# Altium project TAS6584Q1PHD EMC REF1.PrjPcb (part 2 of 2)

## Sheet PowerSupplies_Powerstage.SchDoc: Power Supplies
size Letter; Date: Not shown in title block; ApprovedBy: Not shown in title block; CheckedBy: Not shown in title block; Author: Not shown in title block; CompanyName: Not shown in title block; DrawnBy: LDN; Engineer: Not shown in title block; Organization: Not shown in title block; Address1: Not shown in title block; Address2: Not shown in title block; Address3: Not shown in title block; Address4: Not shown in title block; DocumentNumber: 3; Revision: Use project parameter SCH_Rev; SheetNumber: 3; SheetTotal: 4; PageSetup: Record=PageOptions¦CenterHorizontal=True¦CenterVertical=True¦PrintScale=1.00¦XCorrection=1.00¦YCorrection=1.00¦PrintKind=0¦BorderSize=5000000¦LeftOffset=0¦BottomOffset=0¦Orientation=2¦PaperLength=1000¦PaperWidth=1000¦Scale=100¦PaperSource=15¦PrintQuality=600¦MediaType=1¦DitherType=10¦PaperKind=Letter¦PrintScaleMode=1
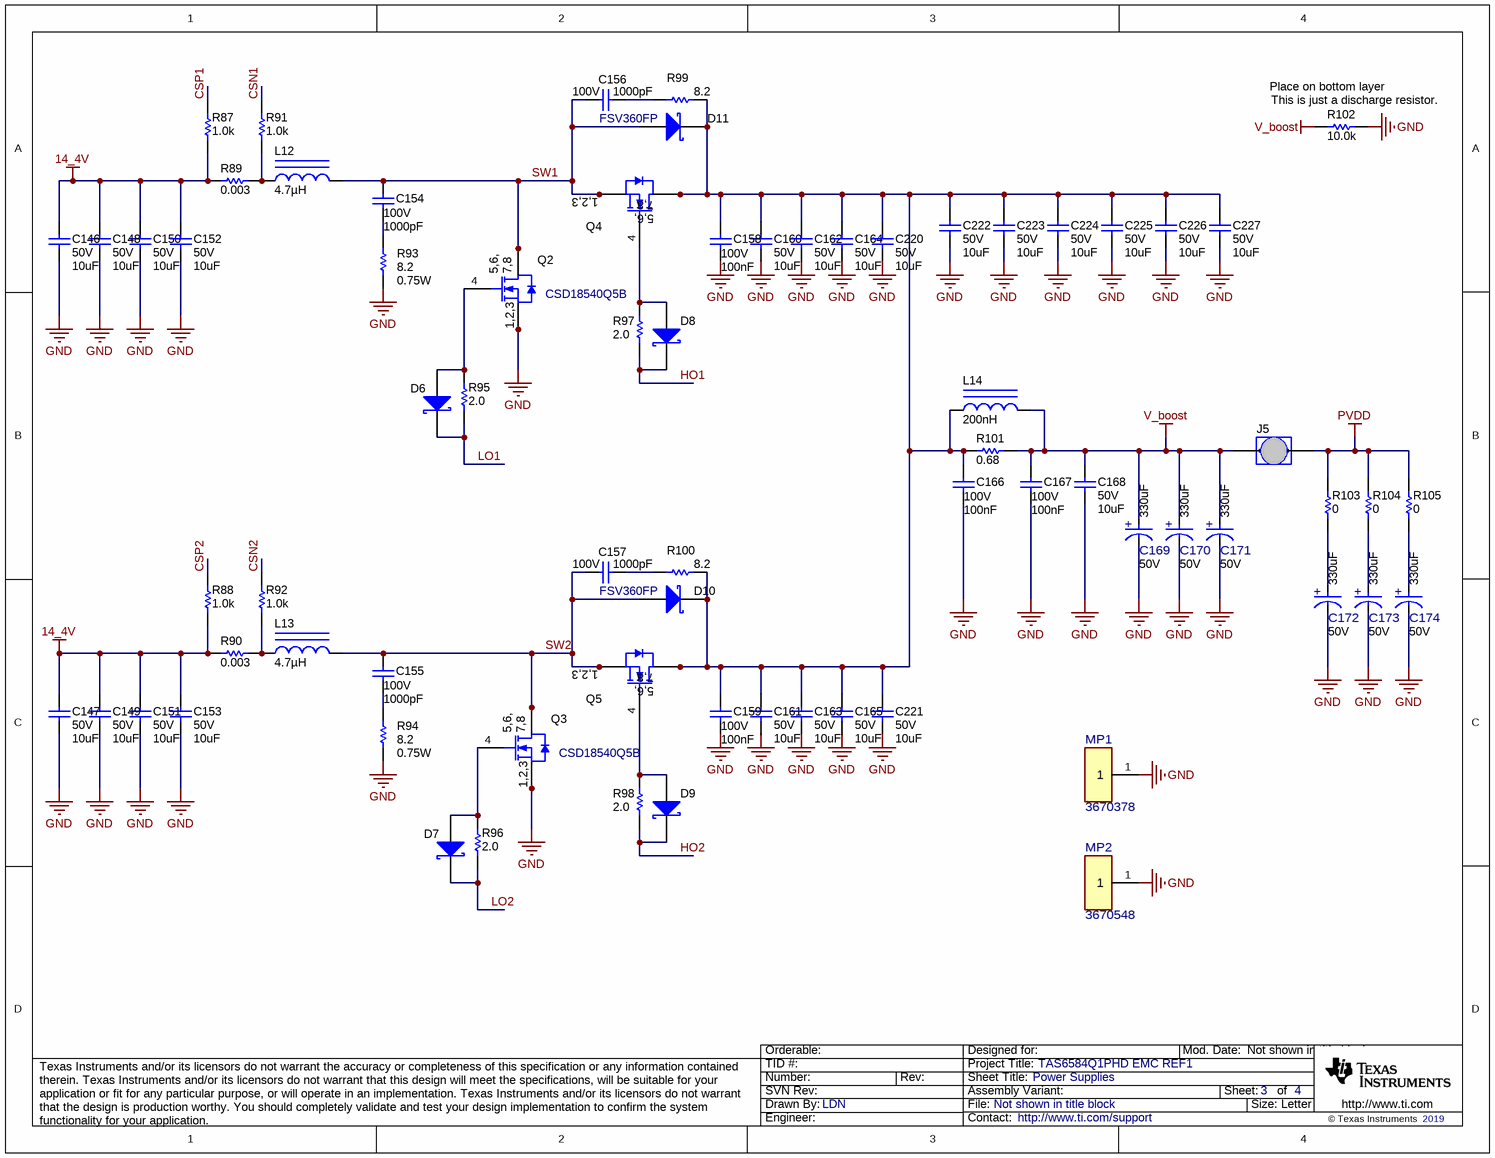
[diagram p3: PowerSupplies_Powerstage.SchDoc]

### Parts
C146  VDC_V: 50V  ValueDisplayed: 10uF  [1210_270]  (hidden comment: GRM32ER71H106KA12L)
C147  VDC_V: 50V  ValueDisplayed: 10uF  [1210_270]  (hidden comment: GRM32ER71H106KA12L)
C148  VDC_V: 50V  ValueDisplayed: 10uF  [1210_270]  (hidden comment: GRM32ER71H106KA12L)
C149  VDC_V: 50V  ValueDisplayed: 10uF  [1210_270]  (hidden comment: GRM32ER71H106KA12L)
C150  VDC_V: 50V  ValueDisplayed: 10uF  [1210_270]  (hidden comment: GRM32ER71H106KA12L)
C151  VDC_V: 50V  ValueDisplayed: 10uF  [1210_270]  (hidden comment: GRM32ER71H106KA12L)
C152  VDC_V: 50V  ValueDisplayed: 10uF  [1210_270]  (hidden comment: GRM32ER71H106KA12L)
C153  VDC_V: 50V  ValueDisplayed: 10uF  [1210_270]  (hidden comment: GRM32ER71H106KA12L)
C154  VDC_V: 100V  ValueDisplayed: 1000pF  [0603L]  (hidden comment: GCM1885C2A102JA16D)
C155  VDC_V: 100V  ValueDisplayed: 1000pF  [0603L]  (hidden comment: GCM1885C2A102JA16D)
C156  VDC_V: 100V  ValueDisplayed: 1000pF  [0603L]  (hidden comment: GCM1885C2A102JA16D)
C157  VDC_V: 100V  ValueDisplayed: 1000pF  [0603L]  (hidden comment: GCM1885C2A102JA16D)
C158  Cap_F: 100nF  VDC_V: 100V  [0603L]  (hidden comment: GRM188R72A104KA35J)
C159  Cap_F: 100nF  VDC_V: 100V  [0603L]  (hidden comment: GRM188R72A104KA35J)
C160  VDC_V: 50V  ValueDisplayed: 10uF  [1210_270]  (hidden comment: GRM32ER71H106KA12L)
C161  VDC_V: 50V  ValueDisplayed: 10uF  [1210_270]  (hidden comment: GRM32ER71H106KA12L)
C162  VDC_V: 50V  ValueDisplayed: 10uF  [1210_270]  (hidden comment: GRM32ER71H106KA12L)
C163  VDC_V: 50V  ValueDisplayed: 10uF  [1210_270]  (hidden comment: GRM32ER71H106KA12L)
C164  VDC_V: 50V  ValueDisplayed: 10uF  [1210_270]  (hidden comment: GRM32ER71H106KA12L)
C165  VDC_V: 50V  ValueDisplayed: 10uF  [1210_270]  (hidden comment: GRM32ER71H106KA12L)
C166  Cap_F: 100nF  VDC_V: 100V  [0603L]  (hidden comment: GRM188R72A104KA35J)
C167  Cap_F: 100nF  VDC_V: 100V  [0603L]  (hidden comment: GRM188R72A104KA35J)
C168  VDC_V: 50V  ValueDisplayed: 10uF  [1210_270]  (hidden comment: GRM32ER71H106KA12L)
C169  ValueDisplayed: 330uF  VDC_V: 50V  [FP-EMZR500ARA331MJA0G_RADIAL-MFG]  (hidden comment: EMZR500ARA331MJA0G)
C170  ValueDisplayed: 330uF  VDC_V: 50V  [FP-EMZR500ARA331MJA0G_RADIAL-MFG]  (hidden comment: EMZR500ARA331MJA0G)
C171  ValueDisplayed: 330uF  VDC_V: 50V  [FP-EMZR500ARA331MJA0G_RADIAL-MFG]  (hidden comment: EMZR500ARA331MJA0G)
C172  ValueDisplayed: 330uF  VDC_V: 50V  [FP-EMZR500ARA331MJA0G_RADIAL-MFG]  (hidden comment: EMZR500ARA331MJA0G)
C173  ValueDisplayed: 330uF  VDC_V: 50V  [FP-EMZR500ARA331MJA0G_RADIAL-MFG]  (hidden comment: EMZR500ARA331MJA0G)
C174  ValueDisplayed: 330uF  VDC_V: 50V  [FP-EMZR500ARA331MJA0G_RADIAL-MFG]  (hidden comment: EMZR500ARA331MJA0G)
C220  VDC_V: 50V  ValueDisplayed: 10uF  [1210_270]  (hidden comment: GRM32ER71H106KA12L)
C221  VDC_V: 50V  ValueDisplayed: 10uF  [1210_270]  (hidden comment: GRM32ER71H106KA12L)
C222  VDC_V: 50V  ValueDisplayed: 10uF  [1210_270]  (hidden comment: GRM32ER71H106KA12L)
C223  VDC_V: 50V  ValueDisplayed: 10uF  [1210_270]  (hidden comment: GRM32ER71H106KA12L)
C224  VDC_V: 50V  ValueDisplayed: 10uF  [1210_270]  (hidden comment: GRM32ER71H106KA12L)
C225  VDC_V: 50V  ValueDisplayed: 10uF  [1210_270]  (hidden comment: GRM32ER71H106KA12L)
C226  VDC_V: 50V  ValueDisplayed: 10uF  [1210_270]  (hidden comment: GRM32ER71H106KA12L)
C227  VDC_V: 50V  ValueDisplayed: 10uF  [1210_270]  (hidden comment: GRM32ER71H106KA12L)
D6  BAT54HT1G  [SOD-323]  (value not drawn)
D7  BAT54HT1G  [SOD-323]  (value not drawn)
D8  BAT54HT1G  [SOD-323]  (value not drawn)
D9  BAT54HT1G  [SOD-323]  (value not drawn)
D10  FSV360FP  [SOD-123HE]
D11  FSV360FP  [SOD-123HE]
J5  (no value)  [HARWIN_S1911-46R]
L12  ValueDisplayed: 4.7µH  [SRP1770TA]  (hidden comment: SRP1770TA-4R7M)
L13  ValueDisplayed: 4.7µH  [SRP1770TA]  (hidden comment: SRP1770TA-4R7M)
L14  ValueDisplayed: 200nH  [SRP7030F_3]  (hidden comment: SRP7030-R20FM)
MP1  3670378  [FP-3670378_RF_SHIELD-MFG]
MP2  3670548  [FP-3670548_RF_SHIELD-MFG]
Q2  CSD18540Q5B  [DNK0008A]
Q3  CSD18540Q5B  [DNK0008A]
Q4  CSD18540Q5B  [DNK0008A]  (value not drawn)
Q5  CSD18540Q5B  [DNK0008A]  (value not drawn)
R87  ValueDisplayed: 1.0k  [0402L]  (hidden comment: CRCW04021K00JNED)
R88  ValueDisplayed: 1.0k  [0402L]  (hidden comment: CRCW04021K00JNED)
R89  ValueDisplayed: 0.003  [PA2512]  (hidden comment: PA2512FKF070R003E)
R90  ValueDisplayed: 0.003  [PA2512]  (hidden comment: PA2512FKF070R003E)
R91  ValueDisplayed: 1.0k  [0402L]  (hidden comment: CRCW04021K00JNED)
R92  ValueDisplayed: 1.0k  [0402L]  (hidden comment: CRCW04021K00JNED)
R93  Value2: 0.75W  ValueDisplayed: 8.2  [2010]  (hidden comment: CRCW20108R20JNEF)
R94  Value2: 0.75W  ValueDisplayed: 8.2  [2010]  (hidden comment: CRCW20108R20JNEF)
R95  ValueDisplayed: 2.0  [0603]  (hidden comment: CRCW06032R00JNEA)
R96  ValueDisplayed: 2.0  [0603]  (hidden comment: CRCW06032R00JNEA)
R97  ValueDisplayed: 2.0  [0603]  (hidden comment: CRCW06032R00JNEA)
R98  ValueDisplayed: 2.0  [0603]  (hidden comment: CRCW06032R00JNEA)
R99  ValueDisplayed: 8.2  [2010]  (hidden comment: CRCW20108R20JNEF)
R100  ValueDisplayed: 8.2  [2010]  (hidden comment: CRCW20108R20JNEF)
R101  ValueDisplayed: 0.68  [2512]  (hidden comment: ERJ-1TRQJR68U)
R102  ValueDisplayed: 10.0k  [2512]  (hidden comment: CRCW251210K0FKEG)
R103  ValueDisplayed: 0  [1210]  (hidden comment: MCR25JZHJ000)
R104  ValueDisplayed: 0  [1210]  (hidden comment: MCR25JZHJ000)
R105  ValueDisplayed: 0  [1210]  (hidden comment: MCR25JZHJ000)

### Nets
14_4V: C146.1 C147.1 C148.1 C149.1 C150.1 C151.1 C152.1 C153.1 R87.1 R88.1 R89.1 R90.1
GND: C146.2 C147.2 C148.2 C149.2 C150.2 C151.2 C152.2 C153.2 C158.2 C159.2 C160.2 C161.2 C162.2 C163.2 C164.2 C165.2 C166.2 C167.2 C168.2 C169.1(CATHODE) C170.1(CATHODE) C171.1(CATHODE) C172.1(CATHODE) C173.1(CATHODE) C174.1(CATHODE) C220.2 C221.2 C222.2 C223.2 C224.2 C225.2 C226.2 C227.2 MP1.1 MP2.1 Q2.1(S) Q2.2(S) Q2.3(S) Q3.1(S) Q3.2(S) Q3.3(S) R93.1 R94.1 R102.2
PVDD: J5.2 R103.2 R104.2 R105.2
V_boost: C167.1 C168.1 C169.2(ANODE) C170.2(ANODE) C171.2(ANODE) J5.1 L14.2 R101.2 R102.1
CSN1: R91.2
CSN2: R92.2
CSP1: R87.2
CSP2: R88.2
HO1: D8.1(K) R97.1
HO2: D9.1(K) R98.1
LO1: D6.1(K) R95.1
LO2: D7.1(K) R96.1
SW1: C154.1 C156.1 D11.2(A) L12.2 Q2.5(D) Q2.6(D) Q2.7(D) Q2.8(D) Q2.9(D) Q4.1(S) Q4.2(S) Q4.3(S)
SW2: C155.1 C157.1 D10.2(A) L13.2 Q3.5(D) Q3.6(D) Q3.7(D) Q3.8(D) Q3.9(D) Q5.1(S) Q5.2(S) Q5.3(S)
NetC154_2: C154.2 R93.2
NetC155_2: C155.2 R94.2
NetC156_2: C156.2 R99.1
NetC157_2: C157.2 R100.1
NetC158_1: C158.1 C159.1 C160.1 C161.1 C162.1 C163.1 C164.1 C165.1 C166.1 C220.1 C221.1 C222.1 C223.1 C224.1 C225.1 C226.1 C227.1 D10.1(K) D11.1(K) L14.1 Q4.5(D) Q4.6(D) Q4.7(D) Q4.8(D) Q4.9(D) Q5.5(D) Q5.6(D) Q5.7(D) Q5.8(D) Q5.9(D) R99.2 R100.2 R101.1
NetC172_2: C172.2(ANODE) R103.1
NetC173_2: C173.2(ANODE) R104.1
NetC174_2: C174.2(ANODE) R105.1
NetD6_2: D6.2(A) Q2.4(G) R95.2
NetD7_2: D7.2(A) Q3.4(G) R96.2
NetD8_2: D8.2(A) Q4.4(G) R97.2
NetD9_2: D9.2(A) Q5.4(G) R98.2
NetL12_1: L12.1 R89.2 R91.1
NetL13_1: L13.1 R90.2 R92.1

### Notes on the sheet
- (near R102) Place on bottom layer
- (near R102) This is just a discharge resistor.

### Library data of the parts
C146-C153 C160-C165 C168 C220-C227 = CMP-0009226-3: CAP, CERM, 10 uF, 50 V, +/- 10%, X7R, 1210; Manufacturer: MuRata; TaMin_C: -55°C; Polarized: N; SizeAreaWB_mm2: 14.7; Value1: Unknown; U/M: EA; Value: 10uF; TaMax_C: 125°C; SizeZ_mm: 2.7; SizeX_mm: 3.2; SizeY_mm: 2.5; Cap_Case: 1210; SizeArea_mm2: 8; Cap_F: 10µF; AEC Category: Q200
C154-C157 = CMP-0007131-1: CAP, CERM, 1000 pF, 100 V, +/- 5%, C0G/NP0, AEC-Q200 Grade 1, 0603; Manufacturer: MuRata; TaMin_C: -55°C; Polarized: N; SizeAreaWB_mm2: 4.68; Value1: Unknown; U/M: EA; Value: 1000pF; TaMax_C: 125°C; SizeZ_mm: 1; SizeX_mm: 1.6; SizeY_mm: 0.8; Cap_Case: 0603; SizeArea_mm2: 1.28; AEC Qualified: Y; Cap_F: 1nF; AEC Category: Q200
C158 C159 C166 C167 = CMP-0007470-1: CAP, CERM, 0.1 uF, 100 V, +/- 10%, X7R, 0603; Manufacturer: MuRata; TaMin_C: -55°C; Polarized: N; SizeAreaWB_mm2: 4.68; Value1: Unknown; U/M: EA; Value: 0.1uF; TaMax_C: 125°C; SizeZ_mm: 1; SizeX_mm: 1.6; SizeY_mm: 0.8; Cap_Case: 0603; SizeArea_mm2: 1.28; AEC Category: Q200
C169-C174 = CMP-0093066-1: 330 µF 50 V Aluminum Electrolytic Capacitors Radial, Can - SMD 120mOhm @ 100kHz 2000 Hrs @ 105°C; Manufacturer: United Chemi-Con; Dissipation Factor: 10%; Esr: 0.12; Value: 330µF; AEC Qualified: Yes; AEC Grade: Grade 2; IRMS_A: 900mA; Life: 2000Hours; Tolerance_%: 20%; SizeZ_mm: 10.3mm; Leakage Current: 165uA
D6-D9 = CMP-0028455-1: Diode, Schottky, 30 V, 0.2 A, SOD-323; Manufacturer: ON Semiconductor; Io_A: 200mA; Green_Lifecycle: Active; SizeAreaWB_mm2: 8.695; Vr_V: 30V; Green_REACh: Passed; Value1: 0.2A; U/M: EA; Value: 30V; SizeZ_mm: 1; SizeX_mm: 2.7; SizeY_mm: 1.35; Vf_V: 350mV; Value2: 0.35V; SizeArea_mm2: 3.645; AEC Category: Q101
D10 D11 = CMP-0028825-2: Diode, Schottky, 60 V, 3 A, AEC-Q101, SOD-123HE; Manufacturer: Fairchild Semiconductor; Vf_V: 650mV; SizeArea_mm2: 6.66; Vr_V: 60V; Green_Lifecycle: Not Set; Value: 60V; Value1: 3A; Green_REACh: Incomplete; SizeY_mm: 1.8; Value2: 0.65V; TJmax_C: 150°C; AEC Category: Q101; SizeAreaWB_mm2: 13.16; SizeZ_mm: 1; AEC Qualified: Y; SizeX_mm: 3.7
J5 = CMP-0075020-1: JUMPER TIN SMD; Manufacturer: Harwin; PartNumber: S1911-46R; CNHeader: False; Green_Lifecycle: Active; Green_REACh: Passed; CompType: Jumper SMT
L12 L13 = CMP-0081211-1: Inductor, Shielded, Powdered Iron, 4.7 µH, 25 A, 0.0055 ohm, AEC-Q200 Grade 0, SMD; Manufacturer: Bourns; Isat: 50A @ 30% inductance drop; Irms: 25A @ 40C rise; SizeAreaWB_mm2: 364.77; DCR_ohm: 5.5m; Value: 4.7uH; Imax_A: 25A; SizeZ_mm: 7; SizeX_mm: 17.3; SizeY_mm: 16.9; SizeArea_mm2: 292.37; AEC Qualified: Y; AEC Grade: 0; AEC Category: Q200
L14 = CMP-0056994-1: Inductor, Flat Wire, Powdered Iron, 200 nH, 23 A, 0.0024 ohm, SMD; Manufacturer: Bourns; Isat: 34A @ 20% inductance drop; Irms: 23A @ 40C rise; Green_Lifecycle: NRND; SizeAreaWB_mm2: 81.6; DCR_ohm: 2.4m; Green_REACh: Passed; Value: 200nH; Imax_A: 23A; SizeZ_mm: 3; SizeX_mm: 7.6; SizeY_mm: 6.5; SizeArea_mm2: 49.4; AEC Category: Q200
MP1 = CMP-0093198-1: Manufacturer: Wurth Electronics; SizeZ_mm: 3.2mm; AEC Qualified: No
MP2 = CMP-0093199-1: Manufacturer: Wurth Electronics; AEC Qualified: No; SizeZ_mm: 11.2mm
Q2-Q5 = CMP-0000823-2: MOSFET, N-CH, 60 V, 100 A, DNK0008A (VSON-CLIP-8); Alternate Manufacturer: None; Manufacturer: Texas Instruments; SizeZ_mm: 1; ChType: N; Value2: 41 nC; Value1: 0.003; VdsMax_V: 60V; SizeX_mm: 6; SizeY_mm: 5; Vgs_V: 20V; Value: 60V; Rdson45_ohm: 3.3m; SizeArea_mm2: 30; AEC Category: Q101; IdsMax_A: 100A; SizeAreaWB_mm2: 56; U/M: EA; QgTyp_nC: 41
R87 R88 R91 R92 = CMP-0026852-1: RES, 1.0 k, 5%, 0.063 W, 0402; Manufacturer: Vishay-Dale; Power_W: 63mW; TempCo: 200 ppm/C; Value_Code: 1k00; U/M: EA; Value: 1.0k; EIA_Code: E24; Res_ohm: 1k; SizeX_mm: 1; SizeY_mm: 0.5; SizeZ_mm: 0.6; Value2: 0.063W; VDC_V: 50V; AEC Category: Q200
R89 R90 = CMP-0015833-2: RES, 0.003, 1%, 1 W, AEC-Q200 Grade 0, 2512; Manufacturer: Yageo America; Power_W: 1W; TempCo: 100 ppm/C; Value_Code: 3L000; U/M: EA; Value: 0.003; EIA_Code: E96; Res_ohm: 3m; AEC Qualified: Y; AEC Grade: 0; AEC Category: Q200
R93 R94 = CMP-0016186-1: RES, 8.2, 5%, 0.75 W, AEC-Q200 Grade 0, 2010; Manufacturer: Vishay-Dale; Power_W: 750mW; TempCo: 200 ppm/C; Value_Code: 8R20; U/M: EA; Value: 8.2; EIA_Code: E24; SizeX_mm: 5; SizeY_mm: 2.5; SizeZ_mm: 1.66; SizeArea_mm2: 12.5; AEC Qualified: Y; VDC_V: 400V; AEC Grade: 0; AEC Category: Q200
R95-R98 = CMP-0025776-4: RES, 2.0, 5%, 0.1 W, AEC-Q200 Grade 0, 0603; Manufacturer: Vishay-Dale; Power_W: 100mW; TempCo: 200 ppm/C; Value_Code: 2R00; Value: 2.0; EIA_Code: E24; Res_ohm: 2; SizeX_mm: 1.6; SizeY_mm: 0.8; SizeZ_mm: 1; Value2: 0.1W; SizeArea_mm2: 1.28; AEC Qualified: Y; VDC_V: 75V; AEC Category: Q200; AEC Grade: 0
R99 R100 = CMP-0016186-1: RES, 8.2, 5%, 0.75 W, AEC-Q200 Grade 0, 2010; Manufacturer: Vishay-Dale; Power_W: 750mW; TempCo: 200 ppm/C; Value_Code: 8R20; U/M: EA; Value: 8.2; EIA_Code: E24; SizeX_mm: 5; SizeY_mm: 2.5; SizeZ_mm: 1.66; Value2: 0.75W; SizeArea_mm2: 12.5; AEC Qualified: Y; VDC_V: 400V; AEC Grade: 0; AEC Category: Q200
R101 = CMP-0016021-1: RES, 0.68, 5%, 1 W, 2512; Manufacturer: Panasonic; Power_W: 1W; TempCo: 200 ppm/C; Value_Code: R680; U/M: EA; Value: 0.68; SizeX_mm: 6.3; SizeY_mm: 3.2; SizeZ_mm: 0.71; SizeArea_mm2: 20.16; AEC Category: Q200
R102 = CMP-0015431-1: RES, 10.0 k, 1%, 1 W, AEC-Q200 Grade 0, 2512; Manufacturer: Vishay-Dale; Power_W: 1W; TempCo: 100 ppm/C; Value_Code: 10k0; U/M: EA; Value: 10.0k; EIA_Code: E96; Res_ohm: 10k; SizeX_mm: 6.3; SizeY_mm: 3.2; SizeZ_mm: 0.71; SizeArea_mm2: 20.16; AEC Qualified: Y; VDC_V: 500V; AEC Grade: 0; AEC Category: Q200
R103-R105 = CMP-0015361-2: RES, 0, 5%, 0.25 W, 1210; Manufacturer: Rohm; Power_W: 250mW; TempCo: 20 ppm/C; SizeAreaWB_mm2: 14.7; Value_Code: 0000; U/M: EA; Value: 0; EIA_Code: E24; SizeX_mm: 3.2; SizeY_mm: 2.5; SizeZ_mm: 1.35; Value2: 0.25W; SizeArea_mm2: 8; VDC_V: 200V; AEC Category: Q200

## Sheet SPDIF and Interface.SchDoc: SPDIF I/O
size 431 x 279 mm; Date: Not shown in title block; ApprovedBy: Not shown in title block; CheckedBy: Not shown in title block; Author: Not shown in title block; CompanyName: Not shown in title block; DrawnBy: LDN; Engineer: Not shown in title block; Organization: Not shown in title block; Address1: Not shown in title block; Address2: Not shown in title block; Address3: Not shown in title block; Address4: Not shown in title block; DocumentNumber: 1; SheetNumber: 1; SheetTotal: 4; PageSetup: Record=PageOptions¦CenterHorizontal=True¦CenterVertical=True¦PrintScale=0.98¦XCorrection=1.00¦YCorrection=1.00¦PrintKind=0¦BorderSize=5000000¦LeftOffset=0¦BottomOffset=0¦Orientation=2¦PaperLength=1000¦PaperWidth=1000¦Scale=100¦PaperSource=15¦PrintQuality=-3¦MediaType=1¦DitherType=10¦PrintScaleMode=1¦PaperKind=11 x 17¦PaperIndex=119
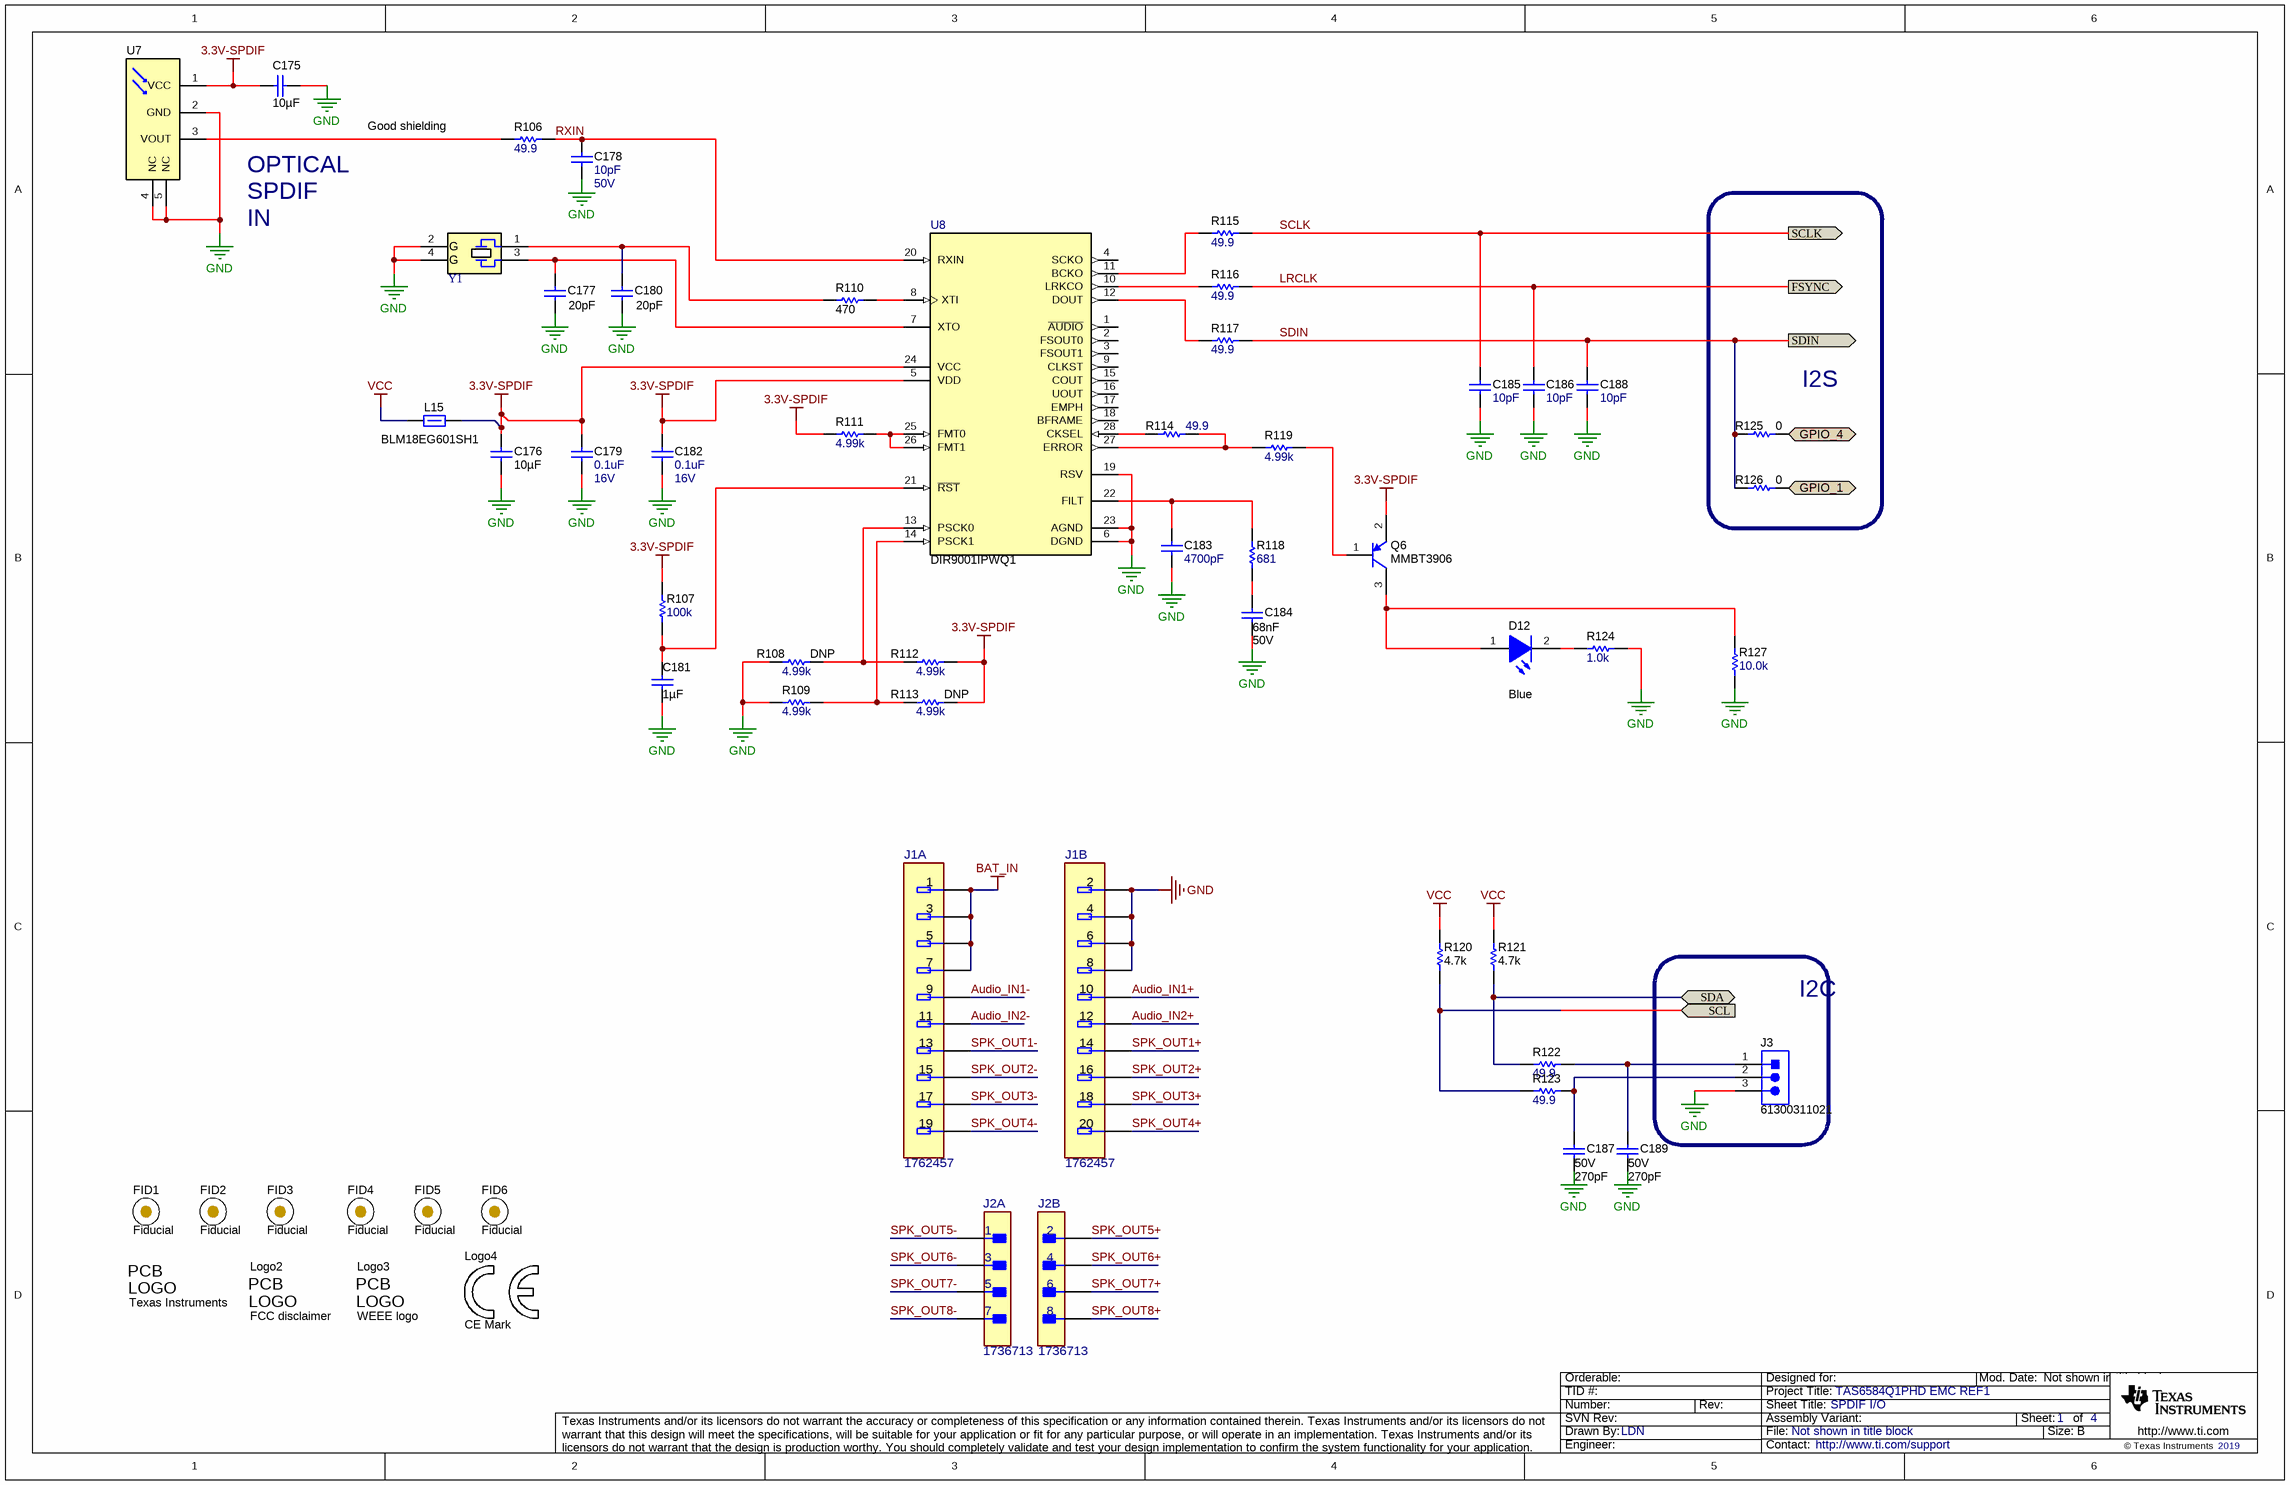
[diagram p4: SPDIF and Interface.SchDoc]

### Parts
C175  Cap_F: 10µF  [0603L]  (hidden comment: GRM188Z71A106MA73D)
C176  Cap_F: 10µF  [0603L]  (hidden comment: GRM188Z71A106MA73D)
C177  ValueDisplayed: 20pF  [0402L]  (hidden comment: GRM1555C1H200JA01D)
C178  ValueDisplayed: 10pF  VDC_V: 50V  [0402L]  (hidden comment: CMP-0006408-2)
C179  ValueDisplayed: 0.1uF  VDC_V: 16V  [0402L]  (hidden comment: CMP-0006641-2)
C180  ValueDisplayed: 20pF  [0402L]  (hidden comment: GRM1555C1H200JA01D)
C181  Cap_F: 1µF  [0603L]  (hidden comment: GCM188R71E105KA64D)
C182  ValueDisplayed: 0.1uF  VDC_V: 16V  [0402L]  (hidden comment: CMP-0006641-2)
C183  ValueDisplayed: 4700pF  [0402L]  (hidden comment: CMP-0006668-2)
C184  Cap_F: 68nF  VDC_V: 50V  [0603L]  (hidden comment: GRM188R71H683KA93D)
C185  ValueDisplayed: 10pF  [0402L]  (hidden comment: CMP-0006408-2)
C186  ValueDisplayed: 10pF  [0402L]  (hidden comment: CMP-0006408-2)
C187  VDC_V: 50V  ValueDisplayed: 270pF  [0603L]  (hidden comment: GRM1885C1H271JA01D)
C188  ValueDisplayed: 10pF  [0402L]  (hidden comment: CMP-0006408-2)
C189  VDC_V: 50V  ValueDisplayed: 270pF  [0603L]  (hidden comment: GRM1885C1H271JA01D)
D12  value Blue  [LED_SMLP12_BLUE]  (hidden comment: CMP-0002838-1)
FID1  CompType: Fiducial  [Fiducial6.4-20]  (hidden comment: DNP)
FID2  CompType: Fiducial  [Fiducial6.4-20]  (hidden comment: DNP)
FID3  CompType: Fiducial  [Fiducial6.4-20]  (hidden comment: DNP)
FID4  CompType: Fiducial  [Fiducial6.4-20]  (hidden comment: DNP)
FID5  CompType: Fiducial  [Fiducial6.4-20]  (hidden comment: DNP)
FID6  CompType: Fiducial  [Fiducial6.4-20]  (hidden comment: DNP)
J1  1762457  [FP-1762457_HDR20-MFG]  (parts A,B of 2)
J2  1736713  [FP-1736713_HDR8-MFG]  (parts A,B of 2)
J3  61300311021  [Wurth_61300311021]
L15  BLM18EG601SH1  [0603L]
Logo1  Texas Instruments  [TI_Stacked_Overlay_Small]  (no BOM)
Logo2  FCC disclaimer  [FCC_disclaimer_stacked]  (no BOM)
Logo3  WEEE logo  [WEEE_Minimum]  (no BOM)
Logo4  CE Mark  [CE_Mark_5mm]  (no BOM)
Q6  MMBT3906  [SOT-23]
R106  ValueDisplayed: 49.9  [0402L]  (hidden comment: CMP-0026404-2)
R107  ValueDisplayed: 100k  [0402L]  (hidden comment: CMP-0025950-3)
R108  DNP  ValueDisplayed: 4.99k  [0402L]
R109  ValueDisplayed: 4.99k  [0402L]  (hidden comment: CMP-0026414-2)
R110  ValueDisplayed: 470  [0402L]  (hidden comment: CRCW0402470RJNED)
R111  ValueDisplayed: 4.99k  [0402L]  (hidden comment: CMP-0026414-2)
R112  ValueDisplayed: 4.99k  [0402L]  (hidden comment: CMP-0026414-2)
R113  DNP  ValueDisplayed: 4.99k  [0402L]
R114  ValueDisplayed: 49.9  [0402L]  (hidden comment: CMP-0026404-2)
R115  ValueDisplayed: 49.9  [0402L]  (hidden comment: CMP-0026404-2)
R116  ValueDisplayed: 49.9  [0402L]  (hidden comment: CMP-0026404-2)
R117  ValueDisplayed: 49.9  [0402L]  (hidden comment: CMP-0026404-2)
R118  ValueDisplayed: 681  [0402L]  (hidden comment: CMP-0026505-2)
R119  ValueDisplayed: 4.99k  [0402L]  (hidden comment: CMP-0026414-2)
R120  ValueDisplayed: 4.7k  [0603L]  (hidden comment: CRCW06034K70JNEA)
R121  ValueDisplayed: 4.7k  [0603L]  (hidden comment: CRCW06034K70JNEA)
R122  ValueDisplayed: 49.9  [0402L]  (hidden comment: CMP-0026404-2)
R123  ValueDisplayed: 49.9  [0402L]  (hidden comment: CMP-0026404-2)
R124  ValueDisplayed: 1.0k  [0402L]  (hidden comment: CRCW04021K00JNED)
R125  ValueDisplayed: 0  [0402L]  (hidden comment: CRCW04020000Z0ED)
R126  ValueDisplayed: 0  [0402L]  (hidden comment: CRCW04020000Z0ED)
R127  ValueDisplayed: 10.0k  [0402L]  (hidden comment: CMP-0025958-3)
U7  CMP-0004896-1  [PLR135_T10]  (value not drawn)
U8  PartNumber: DIR9001IPWQ1  [PW0028A_N]  (hidden comment: TI-DIR9001-Q1-TSSOP_PW-28)
Y1  ABM10-24.576MHZ-E20-T  [XTAL_ABM10]  (value not drawn)

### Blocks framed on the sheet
I2S: R125 R126
I2C: J3

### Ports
FSYNC (out), GPIO_1 (bidir), GPIO_4 (bidir), SCL (in), SCLK (out), SDA (bidir), SDIN (out)

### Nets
3.3V-SPDIF: C175.2 C176.1 C179.2 C182.2 L15.1 Q6.2(E) R107.2 R111.2 R112.1 R113.1 U7.1(VCC) U8.5(VDD) U8.24(VCC)
BAT_IN: J1.1 J1.3 J1.5 J1.7
GND: C175.1 C176.2 C177.2 C178.2 C179.1 C180.2 C181.2 C182.1 C183.2 C184.2 C185.2 C186.2 C187.2 C188.2 C189.2 J1.2 J1.4 J1.6 J1.8 J3.3 R108.2 R109.2 R124.2 R127.1 U7.2(GND) U7.4(NC) U7.5(NC) U8.6(DGND) U8.19(RSV) U8.23(AGND) Y1.2(GND) Y1.4(GND)
VCC: L15.2 R120.2 R121.2
Audio_IN1+: J1.10
Audio_IN1-: J1.9
Audio_IN2+: J1.12
Audio_IN2-: J1.11
GPIO_1: R126.1 ; port GPIO_1
GPIO_4: R125.1 ; port GPIO_4
LRCLK: C186.1 R116.2 ; port FSYNC
RXIN: C178.1 R106.2 U8.20(RXIN)
SCL: R120.1 R123.1 ; port SCL
SCLK: C185.1 R115.2 ; port SCLK
SDA: R121.1 R122.1 ; port SDA
SDIN: C188.1 R117.2 R125.2 R126.2 ; port SDIN
SPK_OUT1+: J1.14
SPK_OUT1-: J1.13
SPK_OUT2+: J1.16
SPK_OUT2-: J1.15
SPK_OUT3+: J1.18
SPK_OUT3-: J1.17
SPK_OUT4+: J1.20
SPK_OUT4-: J1.19
SPK_OUT5+: J2.2
SPK_OUT5-: J2.1
SPK_OUT6+: J2.4
SPK_OUT6-: J2.3
SPK_OUT7+: J2.6
SPK_OUT7-: J2.5
SPK_OUT8+: J2.8
SPK_OUT8-: J2.7
NetC177_1: C177.1 U8.7(XTO) Y1.3
NetC180_1: C180.1 R110.1 Y1.1
NetC181_1: C181.1 R107.1 U8.21(~{RST})
NetC183_1: C183.1 R118.2 U8.22(FILT)
NetC184_1: C184.1 R118.1
NetC187_1: C187.1 J3.2 R123.2
NetC189_1: C189.1 J3.1 R122.2
NetD12_1: D12.1(A) Q6.3(C) R127.2
NetD12_2: D12.2(K) R124.1
NetQ6_1: Q6.1(B) R119.1
NetR106_1: R106.1 U7.3(VOUT)
NetR108_1: R108.1 R112.2 U8.13(PSCK0)
NetR109_1: R109.1 R113.2 U8.14(PSCK1)
NetR110_2: R110.2 U8.8(XTI)
NetR111_1: R111.1 U8.25(FMT0) U8.26(FMT1)
NetR114_1: R114.1 U8.28(CKSEL)
NetR114_2: R114.2 R119.2 U8.27(ERROR)
NetR115_1: R115.1 U8.11(BCKO)
NetR116_1: R116.1 U8.10(LRKCO)
NetR117_1: R117.1 U8.12(DOUT)

Not connected (* = marked no-connect by the designer): U8 1(~{AUDIO}) 2(FSOUT0) 3(FSOUT1) 4(SCKO) 9(CLKST) 15(COUT) 16(UOUT) 17(EMPH) 18(BFRAME)

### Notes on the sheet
- Good shielding
- OPTICAL
- SPDIF
- IN

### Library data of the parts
C175 C176 = CMP-0007497-1: CAP, CERM, 10 uF, 10 V, +/- 20%, X7R, 0603; Manufacturer: MuRata; TaMin_C: -55°C; Polarized: N; SizeAreaWB_mm2: 4.68; Value1: Unknown; U/M: EA; Value: 10uF; TaMax_C: 125°C; SizeZ_mm: 1; SizeX_mm: 1.6; SizeY_mm: 0.8; Cap_Case: 0603; Value2: 10V; SizeArea_mm2: 1.28; AEC Category: Q200
C177 C180 = CMP-0006436-1: CAP, CERM, 20 pF, 50 V, +/- 5%, C0G/NP0, 0402; Manufacturer: MuRata; TaMin_C: -55°C; Polarized: N; SizeAreaWB_mm2: 3; Value1: Unknown; U/M: EA; Value: 20pF; TaMax_C: 125°C; SizeZ_mm: 0.6; SizeX_mm: 1; SizeY_mm: 0.5; Cap_Case: 0402; Value2: 50V; AEC Category: Q200
C178 = CMP-0006408-2: CAP, CERM, 10 pF, 50 V, +/- 5%, C0G/NP0, 0402; PartNumber: GRM1555C1H100JA01D; Manufacturer: MuRata; Polarized: N; Value: 10pF; U/M: EA; Value1: Unknown; TaMin_C: -55°C; TaMax_C: 125°C; Cap_Case: 0402; SizeAreaWB_mm2: 3; SizeZ_mm: 0.6; SizeX_mm: 1; SizeY_mm: 0.5; AEC Category: Q200
C179 C182 = CMP-0006641-2: CAP, CERM, 0.1 uF, 16 V, +/- 10%, X7R, 0402; PartNumber: GRM155R71C104KA88D; Manufacturer: MuRata; Polarized: N; Value: 0.1uF; U/M: EA; Cap_F: 100nF; Value1: Unknown; TaMin_C: -55°C; TaMax_C: 125°C; Cap_Case: 0402; SizeAreaWB_mm2: 3; SizeZ_mm: 0.6; SizeX_mm: 1; SizeY_mm: 0.5; AEC Category: Q200
C181 = CMP-0007139-1: CAP, CERM, 1 uF, 25 V, +/- 10%, X7R, AEC-Q200 Grade 1, 0603; Manufacturer: MuRata; TaMin_C: -55°C; Polarized: N; SizeAreaWB_mm2: 4.68; Value1: Unknown; U/M: EA; Value: 1uF; TaMax_C: 125°C; SizeZ_mm: 1; SizeX_mm: 1.6; SizeY_mm: 0.8; Cap_Case: 0603; Value2: 25V; SizeArea_mm2: 1.28; AEC Qualified: Y; AEC Category: Q200
C183 = CMP-0006668-2: CAP, CERM, 4700 pF, 25 V, +/- 10%, X7R, 0402; PartNumber: GRM155R71E472KA01D; Manufacturer: MuRata; Polarized: N; CompType: Capacitor; Value: 4700pF; U/M: EA; Cap_F: 4.7nF; Value1: Unknown; VDC_V: 25V; TaMin_C: -55°C; TaMax_C: 125°C; Cap_Case: 0402; SizeAreaWB_mm2: 3; SizeZ_mm: 0.6; SizeX_mm: 1; SizeY_mm: 0.5; AEC Category: Q200
C184 = CMP-0007463-1: CAP, CERM, 0.068 uF, 50 V, +/- 10%, X7R, 0603; Manufacturer: MuRata; TaMin_C: -55°C; Polarized: N; SizeAreaWB_mm2: 4.68; Value1: Unknown; U/M: EA; TaMax_C: 125°C; SizeZ_mm: 1; SizeX_mm: 1.6; SizeY_mm: 0.8; Cap_Case: 0603; SizeArea_mm2: 1.28; AEC Category: Q200
C185 C186 C188 = CMP-0006408-2: CAP, CERM, 10 pF, 50 V, +/- 5%, C0G/NP0, 0402; PartNumber: GRM1555C1H100JA01D; Manufacturer: MuRata; Polarized: N; CompType: Capacitor; Value: 10pF; U/M: EA; Value1: Unknown; VDC_V: 50V; TaMin_C: -55°C; TaMax_C: 125°C; Cap_Case: 0402; SizeAreaWB_mm2: 3; SizeZ_mm: 0.6; SizeX_mm: 1; SizeY_mm: 0.5; AEC Category: Q200
C187 C189 = CMP-0007203-1: CAP, CERM, 270 pF, 50 V, +/- 5%, C0G/NP0, 0603; Manufacturer: MuRata; TaMin_C: -55°C; Polarized: N; SizeAreaWB_mm2: 4.68; Value1: Unknown; U/M: EA; Value: 270pF; TaMax_C: 125°C; SizeZ_mm: 1; SizeX_mm: 1.6; SizeY_mm: 0.8; Cap_Case: 0603; SizeArea_mm2: 1.28; AEC Category: Q200
D12 = CMP-0002838-1: LED, Blue, SMD; Manufacturer: Rohm; PartNumber: SMLP12BC7TT86; Type: InGaN; Vf_V: 2.9V; Io_A: 5mA; Tjmax_C: 85°C; Value1: W; U/M: EA
FID1-FID6 = CMP-0077181-1: Fiducial mark.  There is nothing to buy or mount.
J1 = CMP-0087217-1: TERM BLOCK HDR 20POS 5.08MM; Manufacturer: Phoenix Contact; Current_A: 10A; ContactFinish: Tin; Row_Count: 2; Voltage_V: 320V
J2 = CMP-0093062-1: Manufacturer: Phoenix Contact; TaMax_C: +100°C; Voltage_V: 320V; TaMin_C: -40°C; Row_Count: 2; Conn Orientation: Right Angle; ContactFinish: Tin,Nickel; Current_A: 10A; SizeZ_mm: 28.7mm; Conn Gender: Male; Is Female: no; DUT-Pitch_mm: 5.08mm
J3 = CMP-0054795-1: Header, 2.54 mm, 3x1, Gold, R/A, TH; Manufacturer: Wurth Elektronik; Pitch_mm: 2.54; Gender: Male; Shrouded: N; Row_Count: 1; CNHeader: TRUE; CT: FALSE
L15 = CMP-0003347-2: Ferrite Bead, 600 ohm @ 100 MHz, 0.5 A, 0603; Manufacturer: MuRata; Ztyp@1GHz_Ohm: 700; ZTyp@100MHz_Ohm: 600; SizeAreaWB_mm2: 4.68; DCR_ohm: 0.35; Value1: 0.35 ohm; Value: 600 ohm; Imax_A: 500mA; SizeZ_mm: 1; SizeX_mm: 1.6; SizeY_mm: 0.8; Value2: 0.5A; SizeArea_mm2: 1.28
Logo1 = CMP-0074838-1: Texas Instrument Corporate Signature; SymbolCreator: a0412235; Lib Reference: TI_Logo; Library Reference: Logo
Logo2 = CMP-0074847-1: FCC_disclaimer; Library Reference: Logo
Logo3 = CMP-0074769-1
Logo4 = CMP-0074844-1: SymbolCreator: a0412235
Q6 = CMP-0000325-2: Transistor, PNP, 40 V, 0.2 A, SOT-23; Manufacturer: Fairchild Semiconductor; CompType: BJT; PNP: 1; NPN: 0; Vceo_V: 40V; Vcesat1_V: 2.5dV; Value: 40 V; IcRated_A: 2dA; Value1: 0.2 A; HfeMax: 300; TaMin_C: -55°C; TaMax_C: 150°C; U/M: EA; SizeX_mm: 2.5; SizeY_mm: 3; SizeZ_mm: 1.1; SizeArea_mm2: 7.5; AEC Category: Q101; SizeAreaWB_mm2: 14
R106 R114-R117 R122 R123 = CMP-0026404-2: RES, 49.9, 1%, 0.063 W, AEC-Q200 Grade 0, 0402; PartNumber: CRCW040249R9FKED; Manufacturer: Vishay-Dale; Value: 49.9; Value_Code: 49R9; Power_W: 63mW; Value2: 0.063W; VDC_V: 50V; TempCo: 100 ppm/C; EIA_Code: E96; SizeX_mm: 1; SizeY_mm: 0.5; SizeZ_mm: 0.6; AEC Qualified: Y; AEC Category: Q200; AEC Grade: 0
R107 = CMP-0025950-3: RES, 100 k, 1%, 0.063 W, AEC-Q200 Grade 0, 0402; PartNumber: CRCW0402100KFKED; Manufacturer: Vishay-Dale; Value: 100k; Power_W: 63mW; Value2: 0.063W; VDC_V: 50V; TempCo: 100 ppm/C; EIA_Code: E96; SizeX_mm: 1; SizeY_mm: 0.5; SizeZ_mm: 0.6; AEC Qualified: Y; AEC Category: Q200; AEC Grade: 0
R108 R113 = CMP-0026414-2: RES, 4.99 k, 1%, 0.063 W, AEC-Q200 Grade 0, 0402; PartNumber: CRCW04024K99FKED; Manufacturer: Vishay-Dale; CompType: Resistor; Value: 4.99k; Value_Code: 4k99; Power_W: 63mW; Value2: 0.063W; VDC_V: 50V; TempCo: 100 ppm/C; EIA_Code: E96; SizeX_mm: 1; SizeY_mm: 0.5; SizeZ_mm: 0.6; AEC Qualified: Y; AEC Category: Q200; AEC Grade: 0
R109 R111 R112 R119 = CMP-0026414-2: RES, 4.99 k, 1%, 0.063 W, AEC-Q200 Grade 0, 0402; PartNumber: CRCW04024K99FKED; Manufacturer: Vishay-Dale; Value: 4.99k; Value_Code: 4k99; Power_W: 63mW; Value2: 0.063W; VDC_V: 50V; TempCo: 100 ppm/C; EIA_Code: E96; SizeX_mm: 1; SizeY_mm: 0.5; SizeZ_mm: 0.6; AEC Qualified: Y; AEC Category: Q200; AEC Grade: 0
R110 = CMP-0026934-3: RES, 470, 5%, 0.063 W, AEC-Q200 Grade 0, 0402; Manufacturer: Vishay-Dale; Power_W: 63mW; TempCo: 200 ppm/C; Value_Code: 470R; Value: 470; EIA_Code: E24; SizeX_mm: 1; SizeY_mm: 0.5; SizeZ_mm: 0.6; Value2: 0.063W; AEC Qualified: Y; VDC_V: 50V; AEC Category: Q200; AEC Grade: 0
R118 = CMP-0026505-2: RES, 681, 1%, 0.063 W, AEC-Q200 Grade 0, 0402; PartNumber: CRCW0402681RFKED; Manufacturer: Vishay-Dale; Value: 681; Value_Code: 681R; Power_W: 63mW; Value2: 0.063W; VDC_V: 50V; TempCo: 100 ppm/C; EIA_Code: E96; SizeX_mm: 1; SizeY_mm: 0.5; SizeZ_mm: 0.6; AEC Qualified: Y; AEC Category: Q200; AEC Grade: 0
R120 R121 = CMP-0025817-1: RES, 4.7 k, 5%, 0.1 W, 0603; Manufacturer: Vishay-Dale; Power_W: 100mW; TempCo: 200 ppm/C; Value_Code: 4k70; U/M: EA; Value: 4.7k; EIA_Code: E24; SizeX_mm: 1.6; SizeY_mm: 0.8; SizeZ_mm: 1; Value2: 0.1W; SizeArea_mm2: 1.28; VDC_V: 75V; AEC Category: Q200
R124 = CMP-0026852-3: RES, 1.0 k, 5%, 0.063 W, AEC-Q200 Grade 0, 0402; Manufacturer: Vishay-Dale; Power_W: 63mW; TempCo: 200 ppm/C; Value_Code: 1k00; Value: 1.0k; EIA_Code: E24; Res_ohm: 1k; SizeX_mm: 1; SizeY_mm: 0.5; SizeZ_mm: 0.6; Value2: 0.063W; CompType: Resistor; AEC Qualified: Y; VDC_V: 50V; AEC Category: Q200; AEC Grade: 0
R125 R126 = CMP-0026822-3: RES, 0, 5%, 0.063 W, AEC-Q200 Grade 0, 0402; Manufacturer: Vishay-Dale; Power_W: 63mW; TempCo: 200 ppm/C; Value_Code: 0000; Value: 0; EIA_Code: E24; SizeX_mm: 1; SizeY_mm: 0.5; SizeZ_mm: 0.6; Value2: 0.063W; AEC Qualified: Y; VDC_V: 50V; AEC Category: Q200
R127 = CMP-0025958-3: RES, 10.0 k, 1%, 0.063 W, AEC-Q200 Grade 0, 0402; PartNumber: CRCW040210K0FKED; Manufacturer: Vishay-Dale; Value: 10.0k; Res_ohm: 10k; Value_Code: 10k0; Power_W: 63mW; Value2: 0.063W; VDC_V: 50V; TempCo: 100 ppm/C; EIA_Code: E96; SizeX_mm: 1; SizeY_mm: 0.5; SizeZ_mm: 0.6; AEC Qualified: Y; AEC Category: Q200; AEC Grade: 0
U7 = CMP-0004896-1: Photolink- Fiber Optic Receiver, TH; PartNumber: PLR135/T10; Manufacturer: Everlight
U8 = CMP-0028713-1: Automotive Catalog 96-kHz 24-Bit Digital Audio Interface Receiver, 50 ps Jitter, 3.3V, -40 to 85 degC, 28-Pin TSSOP (PW), Green (RoHS & no Sb/Br); Manufacturer: Texas Instruments; SubFamily: Digital Audio Receiver; Jitter(ps): 50; Sampling Rate(Max)(kHz): 108; Supply Voltage(s)(V): 3.3
Y1 = CMP-0004590-1: Crystal, 24.576 MHz, 10pF, SMD; Manufacturer: Abracon Corporation; TaMin_C: -20°C; Frequency Stability: +/-20ppm; U/M: EA; TaMax_C: 70°C

## Sheet ADC.SchDoc
size Letter; Date: Not shown in title block; ApprovedBy: Not shown in title block; CheckedBy: Not shown in title block; Author: Not shown in title block; CompanyName: Not shown in title block; Engineer: Not shown in title block; Organization: Not shown in title block; Address1: Not shown in title block; Address2: Not shown in title block; Address3: Not shown in title block; Address4: Not shown in title block; DocumentNumber: 4; Revision: Use project parameter SCH_Rev; SheetNumber: 4; SheetTotal: 4; PageSetup: Record=PageOptions¦CenterHorizontal=True¦CenterVertical=True¦PrintScale=1.00¦XCorrection=1.00¦YCorrection=1.00¦PrintKind=0¦BorderSize=5000000¦LeftOffset=0¦BottomOffset=0¦Orientation=2¦PaperLength=1000¦PaperWidth=1000¦Scale=100¦PaperSource=15¦PrintQuality=600¦MediaType=1¦DitherType=10¦PaperKind=Letter¦PrintScaleMode=1
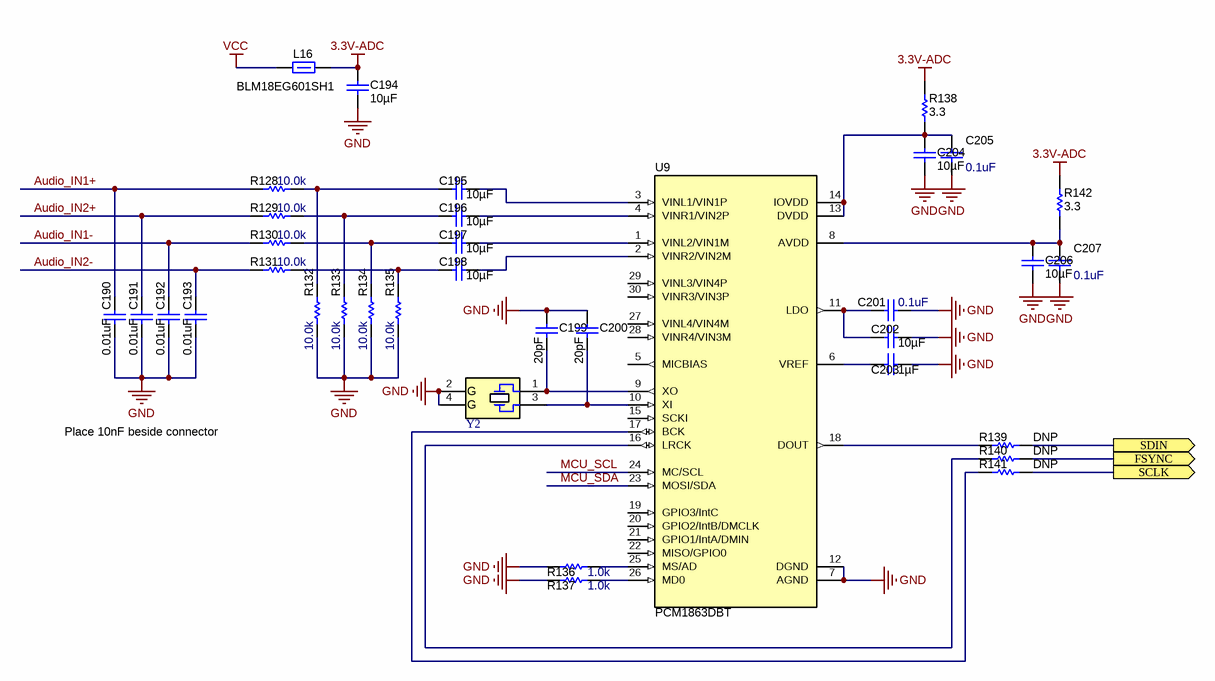
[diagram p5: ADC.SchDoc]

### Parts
C190  ValueDisplayed: 0.01uF  [0603L]  (hidden comment: GRM1885C1H103JA01D)
C191  ValueDisplayed: 0.01uF  [0603L]  (hidden comment: GRM1885C1H103JA01D)
C192  ValueDisplayed: 0.01uF  [0603L]  (hidden comment: GRM1885C1H103JA01D)
C193  ValueDisplayed: 0.01uF  [0603L]  (hidden comment: GRM1885C1H103JA01D)
C194  Cap_F: 10µF  [0603L]  (hidden comment: GRM188Z71A106MA73D)
C195  Cap_F: 10µF  [0603L]  (hidden comment: GRM188Z71A106MA73D)
C196  Cap_F: 10µF  [0603L]  (hidden comment: GRM188Z71A106MA73D)
C197  Cap_F: 10µF  [0603L]  (hidden comment: GRM188Z71A106MA73D)
C198  Cap_F: 10µF  [0603L]  (hidden comment: GRM188Z71A106MA73D)
C199  ValueDisplayed: 20pF  [0402L]  (hidden comment: GRM1555C1H200JA01D)
C200  ValueDisplayed: 20pF  [0402L]  (hidden comment: GRM1555C1H200JA01D)
C201  ValueDisplayed: 0.1uF  [0402L]  (hidden comment: CMP-0006641-2)
C202  Cap_F: 10µF  [0603L]  (hidden comment: GRM188Z71A106MA73D)
C203  Cap_F: 1µF  [0603L]  (hidden comment: GCM188R71E105KA64D)
C204  Cap_F: 10µF  [0603L]  (hidden comment: GRM188Z71A106MA73D)
C205  ValueDisplayed: 0.1uF  [0402L]  (hidden comment: CMP-0006641-2)
C206  Cap_F: 10µF  [0603L]  (hidden comment: GRM188Z71A106MA73D)
C207  ValueDisplayed: 0.1uF  [0402L]  (hidden comment: CMP-0006641-2)
L16  BLM18EG601SH1  [0603L]
R128  ValueDisplayed: 10.0k  [0402L]  (hidden comment: CMP-0025958-3)
R129  ValueDisplayed: 10.0k  [0402L]  (hidden comment: CMP-0025958-3)
R130  ValueDisplayed: 10.0k  [0402L]  (hidden comment: CMP-0025958-3)
R131  ValueDisplayed: 10.0k  [0402L]  (hidden comment: CMP-0025958-3)
R132  ValueDisplayed: 10.0k  [0402L]  (hidden comment: CMP-0025958-3)
R133  ValueDisplayed: 10.0k  [0402L]  (hidden comment: CMP-0025958-3)
R134  ValueDisplayed: 10.0k  [0402L]  (hidden comment: CMP-0025958-3)
R135  ValueDisplayed: 10.0k  [0402L]  (hidden comment: CMP-0025958-3)
R136  ValueDisplayed: 1.0k  [0402L]  (hidden comment: CRCW04021K00JNED)
R137  ValueDisplayed: 1.0k  [0402L]  (hidden comment: CRCW04021K00JNED)
R138  ValueDisplayed: 3.3  [0603L]  (hidden comment: CRCW06033R30JNEA)
R139  DNP  [0402L]
R140  DNP  [0402L]
R141  DNP  [0402L]
R142  ValueDisplayed: 3.3  [0603L]  (hidden comment: CRCW06033R30JNEA)
U9  PCM1863DBT  [DBT0030A_N]
Y2  ABM10-24.576MHZ-E20-T  [XTAL_ABM10]  (value not drawn)

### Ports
FSYNC (out), SCLK (out), SDIN (out)

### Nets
3.3V-ADC: C194.1 L16.1 R138.2 R142.2
GND: C190.2 C191.2 C192.2 C193.2 C194.2 C199.1 C200.1 C201.1 C202.2 C203.2 C204.2 C205.1 C206.2 C207.1 R132.1 R133.1 R134.1 R135.1 R136.1 R137.1 U9.7(AGND) U9.12(DGND) Y2.2(GND) Y2.4(GND)
VCC: L16.2
Audio_IN1+: C190.1 R128.2
Audio_IN1-: C192.1 R130.2
Audio_IN2+: C191.1 R129.2
Audio_IN2-: C193.1 R131.2
LRCLK: R140.1 ; port FSYNC
MCU_SCL: U9.24(MC/SCL)
MCU_SDA: U9.23(MOSI/SDA)
SCLK: R141.1 ; port SCLK
SDIN: R139.1 ; port SDIN
NetC195_1: C195.1 R128.1 R132.2
NetC195_2: C195.2 U9.3(VINL1/VIN1P)
NetC196_1: C196.1 R129.1 R133.2
NetC196_2: C196.2 U9.4(VINR1/VIN2P)
NetC197_1: C197.1 R130.1 R134.2
NetC197_2: C197.2 U9.1(VINL2/VIN1M)
NetC198_1: C198.1 R131.1 R135.2
NetC198_2: C198.2 U9.2(VINR2/VIN2M)
NetC199_2: C199.2 U9.9(XO) Y2.1
NetC200_2: C200.2 U9.10(XI) Y2.3
NetC201_2: C201.2 C202.1 U9.11(LDO)
NetC203_1: C203.1 U9.6(VREF)
NetC204_1: C204.1 C205.2 R138.1 U9.13(DVDD) U9.14(IOVDD)
NetC206_1: C206.1 C207.2 R142.1 U9.8(AVDD)
NetR136_2: R136.2 U9.25(MS/AD)
NetR137_2: R137.2 U9.26(MD0)
NetR139_2: R139.2 U9.18(DOUT)
NetR140_2: R140.2 U9.16(LRCK)
NetR141_2: R141.2 U9.17(BCK)

Not connected (* = marked no-connect by the designer): U9 5(MICBIAS) 15(SCKI) 19(GPIO3/IntC) 20(GPIO2/IntB/DMCLK) 21(GPIO1/IntA/DMIN) 22(MISO/GPIO0) 27(VINL4/VIN4M) 28(VINR4/VIN3M) 29(VINL3/VIN4P) 30(VINR3/VIN3P)

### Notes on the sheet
- Place 10nF beside connector

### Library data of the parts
C190-C193 = CMP-0007174-3: CAP, CERM, 0.01 uF, 50 V, +/- 5%, C0G/NP0, 0603; Manufacturer: MuRata; TaMin_C: -55°C; Polarized: N; SizeAreaWB_mm2: 4.68; Value1: Unknown; U/M: EA; Value: 0.01uF; TaMax_C: 125°C; SizeZ_mm: 1; SizeX_mm: 1.6; SizeY_mm: 0.8; Cap_Case: 0603; Value2: 50V; SizeArea_mm2: 1.28; Cap_F: 10nF; AEC Category: Q200
C194-C198 C202 C204 C206 = CMP-0007497-1: as C175 on sheet SPDIF and Interface
C199 C200 = CMP-0006436-1: as C177 on sheet SPDIF and Interface
C201 C205 C207 = CMP-0006641-2: CAP, CERM, 0.1 uF, 16 V, +/- 10%, X7R, 0402; PartNumber: GRM155R71C104KA88D; Manufacturer: MuRata; Polarized: N; Value: 0.1uF; U/M: EA; Cap_F: 100nF; Value1: Unknown; VDC_V: 16V; TaMin_C: -55°C; TaMax_C: 125°C; Cap_Case: 0402; SizeAreaWB_mm2: 3; SizeZ_mm: 0.6; SizeX_mm: 1; SizeY_mm: 0.5; AEC Category: Q200
C203 = CMP-0007139-1: as C181 on sheet SPDIF and Interface
L16 = CMP-0003347-2: as L15 on sheet SPDIF and Interface
R128-R135 = CMP-0025958-3: as R127 on sheet SPDIF and Interface
R136 R137 = CMP-0026852-3: as R124 on sheet SPDIF and Interface
R138 R142 = CMP-0025805-4: RES, 3.3, 5%, 0.1 W, AEC-Q200 Grade 0, 0603; Manufacturer: Vishay-Dale; Power_W: 100mW; TempCo: 200 ppm/C; Value_Code: 3R30; Value: 3.3; EIA_Code: E24; SizeX_mm: 1.6; SizeY_mm: 0.8; SizeZ_mm: 1; Value2: 0.1W; SizeArea_mm2: 1.28; AEC Qualified: Y; VDC_V: 75V; AEC Category: Q200; AEC Grade: 0
R139-R141 = CMP-0026822-3: RES, 0, 5%, 0.063 W, AEC-Q200 Grade 0, 0402; Manufacturer: Vishay-Dale; PartNumber: CRCW04020000Z0ED; Power_W: 63mW; TempCo: 200 ppm/C; Value_Code: 0000; Value: 0; EIA_Code: E24; SizeX_mm: 1; SizeY_mm: 0.5; SizeZ_mm: 0.6; Value2: 0.063W; AEC Qualified: Y; VDC_V: 50V; AEC Category: Q200
U9 = CMP-0065622-1: 110 dB 2ch S/W Controlled Audio ADC With Universal Front End, DBT0030A (TSSOP-30); Alternate Manufacturer: Texas Instruments; Green_Lifecycle: Active; SizeAreaWB_mm2: 82.32; Green_REACh: Passed; U/M: EA; SizeZ_mm: 1.2; SizeX_mm: 6.4; SizeY_mm: 7.8; SizeArea_mm2: 49.92; CompType: IC
Y2 = CMP-0004590-1: as Y1 on sheet SPDIF and Interface

## Sheet MCU.SchDoc
size Letter; Date: Not shown in title block; ApprovedBy: Not shown in title block; CheckedBy: Not shown in title block; Author: Not shown in title block; CompanyName: Not shown in title block; Engineer: Not shown in title block; Organization: Not shown in title block; Address1: Not shown in title block; Address2: Not shown in title block; Address3: Not shown in title block; Address4: Not shown in title block; DocumentNumber: 4; Revision: Use project parameter SCH_Rev; SheetNumber: 4; SheetTotal: 4; PageSetup: Record=PageOptions¦CenterHorizontal=True¦CenterVertical=True¦PrintScale=1.00¦XCorrection=1.00¦YCorrection=1.00¦PrintKind=0¦BorderSize=5000000¦LeftOffset=0¦BottomOffset=0¦Orientation=2¦PaperLength=1000¦PaperWidth=1000¦Scale=100¦PaperSource=15¦PrintQuality=600¦MediaType=1¦DitherType=10¦PaperKind=Letter¦PrintScaleMode=1
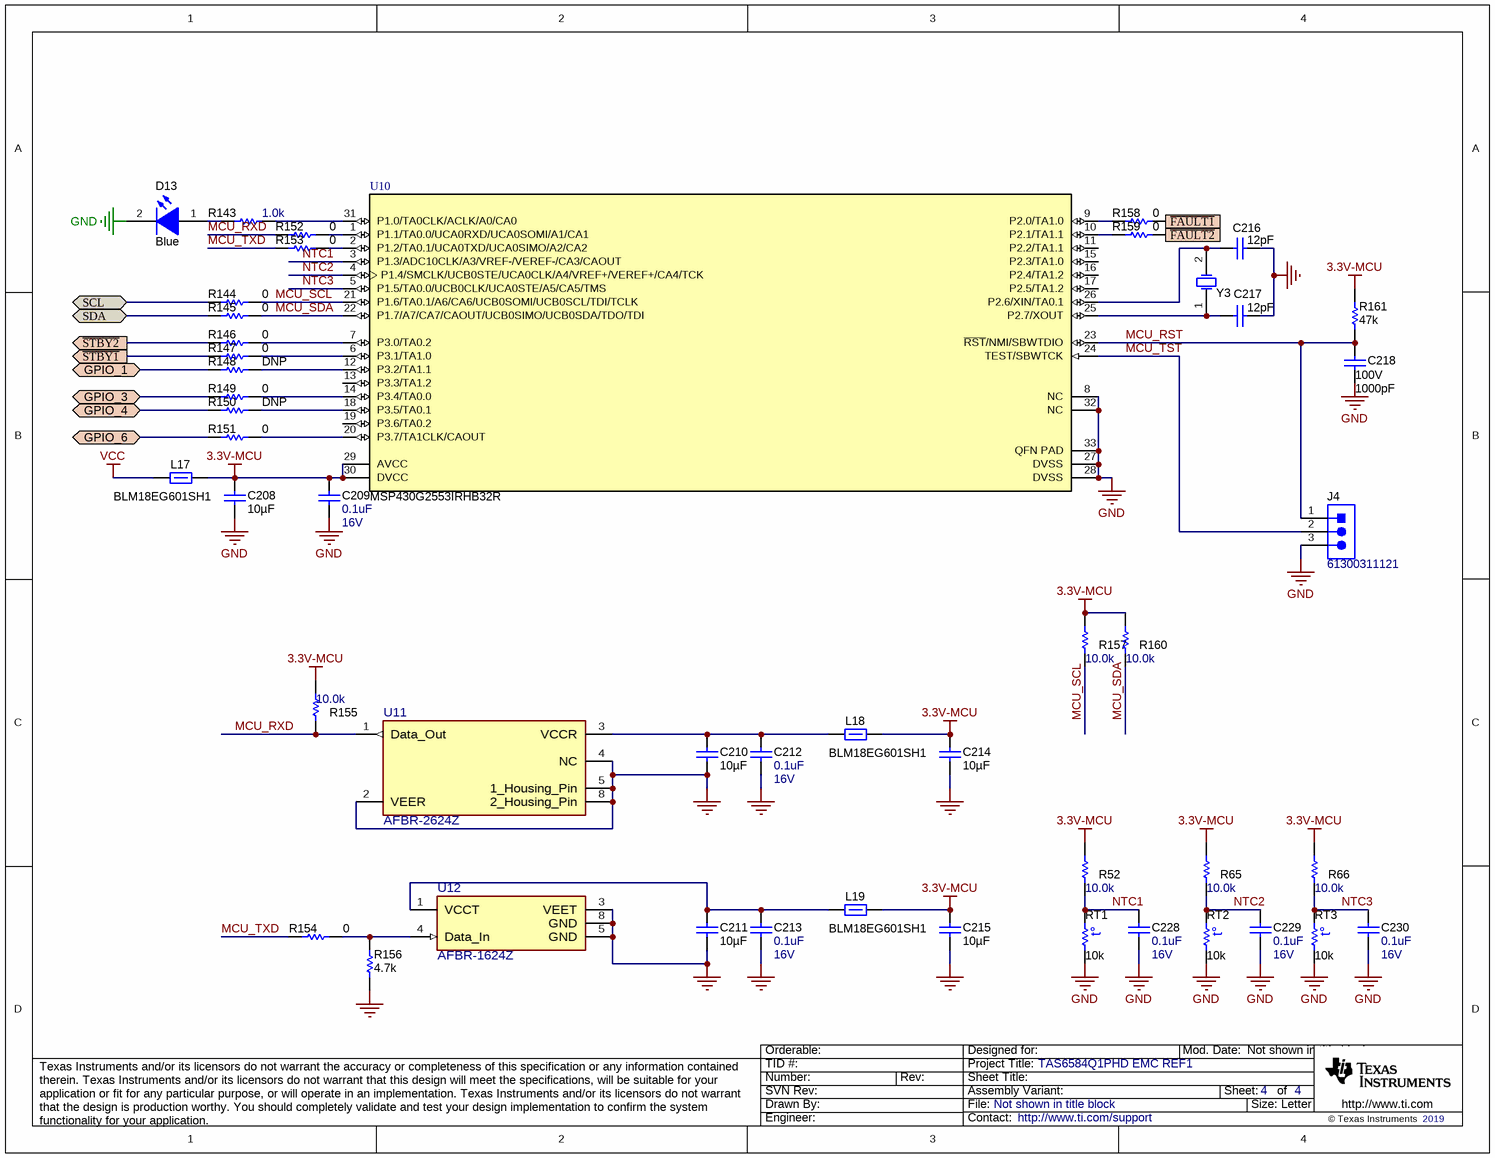
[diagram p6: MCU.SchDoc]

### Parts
C208  Cap_F: 10µF  [0603L]  (hidden comment: GRM188Z71A106MA73D)
C209  ValueDisplayed: 0.1uF  VDC_V: 16V  [0402L]  (hidden comment: CMP-0006641-2)
C210  Cap_F: 10µF  [0603L]  (hidden comment: GRM188Z71A106MA73D)
C211  Cap_F: 10µF  [0603L]  (hidden comment: GRM188Z71A106MA73D)
C212  ValueDisplayed: 0.1uF  VDC_V: 16V  [0402L]  (hidden comment: CMP-0006641-2)
C213  ValueDisplayed: 0.1uF  VDC_V: 16V  [0402L]  (hidden comment: CMP-0006641-2)
C214  Cap_F: 10µF  [0603L]  (hidden comment: GRM188Z71A106MA73D)
C215  Cap_F: 10µF  [0603L]  (hidden comment: GRM188Z71A106MA73D)
C216  ValueDisplayed: 12pF  [0402L]  (hidden comment: GRM1555C1E120JA01D)
C217  ValueDisplayed: 12pF  [0402L]  (hidden comment: GRM1555C1E120JA01D)
C218  VDC_V: 100V  ValueDisplayed: 1000pF  [0603L]  (hidden comment: GCM1885C2A102JA16D)
C228  ValueDisplayed: 0.1uF  VDC_V: 16V  [0402L]  (hidden comment: CMP-0006641-2)
C229  ValueDisplayed: 0.1uF  VDC_V: 16V  [0402L]  (hidden comment: CMP-0006641-2)
C230  ValueDisplayed: 0.1uF  VDC_V: 16V  [0402L]  (hidden comment: CMP-0006641-2)
D13  value Blue  [LED_SMLP12_BLUE]  (hidden comment: CMP-0002838-1)
J4  61300311121  [WURTH_61300311121]
L17  BLM18EG601SH1  [0603L]
L18  BLM18EG601SH1  [0603L]
L19  BLM18EG601SH1  [0603L]
R52  ValueDisplayed: 10.0k  [0402L]  (hidden comment: CMP-0025958-3)
R65  ValueDisplayed: 10.0k  [0402L]  (hidden comment: CMP-0025958-3)
R66  ValueDisplayed: 10.0k  [0402L]  (hidden comment: CMP-0025958-3)
R143  ValueDisplayed: 1.0k  [0402L]  (hidden comment: CRCW04021K00JNED)
R144  ValueDisplayed: 0  [0402L]  (hidden comment: CRCW04020000Z0ED)
R145  ValueDisplayed: 0  [0402L]  (hidden comment: CRCW04020000Z0ED)
R146  ValueDisplayed: 0  [0402L]  (hidden comment: CRCW04020000Z0ED)
R147  ValueDisplayed: 0  [0402L]  (hidden comment: CRCW04020000Z0ED)
R148  DNP  [0402L]
R149  ValueDisplayed: 0  [0402L]  (hidden comment: CRCW04020000Z0ED)
R150  DNP  [0402L]
R151  ValueDisplayed: 0  [0402L]  (hidden comment: CRCW04020000Z0ED)
R152  ValueDisplayed: 0  [0402L]  (hidden comment: CRCW04020000Z0ED)
R153  ValueDisplayed: 0  [0402L]  (hidden comment: CRCW04020000Z0ED)
R154  ValueDisplayed: 0  [0402L]  (hidden comment: CRCW04020000Z0ED)
R155  ValueDisplayed: 10.0k  [0402L]  (hidden comment: CMP-0025958-3)
R156  ValueDisplayed: 4.7k  [0603L]  (hidden comment: CRCW06034K70JNEA)
R157  ValueDisplayed: 10.0k  [0402L]  (hidden comment: CMP-0025958-3)
R158  ValueDisplayed: 0  [0402L]  (hidden comment: CRCW04020000Z0ED)
R159  ValueDisplayed: 0  [0402L]  (hidden comment: CRCW04020000Z0ED)
R160  ValueDisplayed: 10.0k  [0402L]  (hidden comment: CMP-0025958-3)
R161  ValueDisplayed: 47k  [0402L]  (hidden comment: CRCW040247K0JNED)
RT1  value 10k  [0603S]  (hidden comment: NCP18XH103D03RB)
RT2  value 10k  [0603S]  (hidden comment: NCP18XH103D03RB)
RT3  value 10k  [0603S]  (hidden comment: NCP18XH103D03RB)
U10  MSP430G2553IRHB32R  [RHB0032E]
U11  AFBR-2624Z  [FP-AFBR-2624Z_PTH_RX_12MM2_18MM8-MFG]
U12  AFBR-1624Z  [FP-AFBR-1624Z_PTH_TX_18MM8_12MM2-MFG]
Y3  ECS-.327-12.5-34B-TR  [ECS_ECX_31B]  (value not drawn)

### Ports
GPIO_1 (bidir), GPIO_3 (bidir), GPIO_4 (bidir), GPIO_6 (bidir), SCL (bidir), SDA (bidir), ~{FAULT1} (in), ~{FAULT2} (in), ~{STBY1} (out), ~{STBY2} (out)

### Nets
3.3V-MCU: C208.1 C209.2 C214.1 C215.1 L17.1 L18.1 L19.1 R52.2 R65.2 R66.2 R155.2 R157.2 R160.2 R161.2 U10.29(AVCC) U10.30(DVCC)
GND: C208.2 C209.1 C210.2 C211.2 C212.1 C213.1 C214.2 C215.2 C216.1 C217.1 C218.2 C228.1 C229.1 C230.1 D13.2(K) J4.3 R156.1 RT1.1 RT2.1 RT3.1 U10.8(NC) U10.27(DVSS) U10.28(DVSS) U10.32(NC) U10.33(QFN_PAD) U11.2(VEER) U11.4(NC) U11.5(1_Housing_Pin) U11.8(2_Housing_Pin) U12.3(VEET) U12.5(GND) U12.8(GND)
VCC: L17.2
~{FAULT1}: R158.1 ; port ~{FAULT1}
~{FAULT2}: R159.1 ; port ~{FAULT2}
~{STBY1}: R147.2 ; port ~{STBY1}
~{STBY2}: R146.2 ; port ~{STBY2}
GPIO_1: R148.2 ; port GPIO_1
GPIO_3: R149.2 ; port GPIO_3
GPIO_4: R150.2 ; port GPIO_4
GPIO_6: R151.2 ; port GPIO_6
MCU_RST: C218.1 J4.1 R161.1 U10.23(~{RST}/NMI/SBWTDIO)
MCU_RXD: R152.2 R155.1 U11.1(Data_Out)
MCU_SCL: R144.1 R157.1 U10.21(P1.6/TA0.1/A6/CA6/UCB0SOMI/UCB0SCL/TDI/TCLK)
MCU_SDA: R145.1 R160.1 U10.22(P1.7/A7/CA7/CAOUT/UCB0SIMO/UCB0SDA/TDO/TDI)
MCU_TST: J4.2 U10.24(TEST/SBWTCK)
MCU_TXD: R153.2 R154.2
NTC1: C228.2 R52.1 RT1.2 U10.3(P1.3/ADC10CLK/A3/VREF-/VEREF-/CA3/CAOUT)
NTC2: C229.2 R65.1 RT2.2 U10.4(P1.4/SMCLK/UCB0STE/UCA0CLK/A4/VREF+/VEREF+/CA4/TCK)
NTC3: C230.2 R66.1 RT3.2 U10.5(P1.5/TA0.0/UCB0CLK/UCA0STE/A5/CA5/TMS)
SCL: R144.2 ; port SCL
SDA: R145.2 ; port SDA
NetC210_1: C210.1 C212.2 L18.2 U11.3(VCCR)
NetC211_1: C211.1 C213.2 L19.2 U12.1(VCCT)
NetC216_2: C216.2 U10.26(P2.6/XIN/TA0.1) Y3.2(OSC2)
NetC217_2: C217.2 U10.25(P2.7/XOUT) Y3.1(OSC1)
NetD13_1: D13.1(A) R143.2
NetR143_1: R143.1 U10.31(P1.0/TA0CLK/ACLK/A0/CA0)
NetR146_1: R146.1 U10.7(P3.0/TA0.2)
NetR147_1: R147.1 U10.6(P3.1/TA1.0)
NetR148_1: R148.1 U10.12(P3.2/TA1.1)
NetR149_1: R149.1 U10.14(P3.4/TA0.0)
NetR150_1: R150.1 U10.18(P3.5/TA0.1)
NetR151_1: R151.1 U10.20(P3.7/TA1CLK/CAOUT)
NetR152_1: R152.1 U10.1(P1.1/TA0.0/UCA0RXD/UCA0SOMI/A1/CA1)
NetR153_1: R153.1 U10.2(P1.2/TA0.1/UCA0TXD/UCA0SIMO/A2/CA2)
NetR154_1: R154.1 R156.2 U12.4(Data_In)
NetR158_2: R158.2 U10.9(P2.0/TA1.0)
NetR159_2: R159.2 U10.10(P2.1/TA1.1)

Not connected (* = marked no-connect by the designer): U10 11(P2.2/TA1.1) 13(P3.3/TA1.2) 15(P2.3/TA1.0) 16(P2.4/TA1.2) 17(P2.5/TA1.2) 19(P3.6/TA0.2)

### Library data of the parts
C208 C210 C211 C214 C215 = CMP-0007497-1: as C175 on sheet SPDIF and Interface
C209 C212 C213 C228-C230 = CMP-0006641-2: as C179 on sheet SPDIF and Interface
C216 C217 = CMP-0006375-1: CAP, CERM, 12 pF, 25 V, +/- 5%, C0G/NP0, 0402; Manufacturer: MuRata; TaMin_C: -55°C; Polarized: N; SizeAreaWB_mm2: 3; Value1: Unknown; U/M: EA; Value: 12pF; TaMax_C: 125°C; SizeZ_mm: 0.6; SizeX_mm: 1; SizeY_mm: 0.5; Cap_Case: 0402; Value2: 25V; AEC Category: Q200
C218 = CMP-0007131-1: as C154 on sheet PowerSupplies_Powerstage
D13 = CMP-0002838-1: as D12 on sheet SPDIF and Interface
J4 = CMP-0054796-2: Header, 2.54 mm, 3x1, Gold, TH; Manufacturer: Wurth Elektronik; Pitch_mm: 2.54; Green_Lifecycle: Active; Cert_UL: Y; Shrouded: N; Green_REACh: Passed; Gender: Male; Row_Count: 1
L17-L19 = CMP-0003347-2: as L15 on sheet SPDIF and Interface
R52 R65 R66 R155 R157 R160 = CMP-0025958-3: as R127 on sheet SPDIF and Interface
R143 = CMP-0026852-3: as R124 on sheet SPDIF and Interface
R144-R147 R149 R151-R154 R158 R159 = CMP-0026822-3: as R125 on sheet SPDIF and Interface
R148 R150 = CMP-0026822-3: as R139-R141 on sheet ADC
R156 = CMP-0025817-1: as R120 on sheet SPDIF and Interface
R161 = CMP-0026935-3: RES, 47 k, 5%, 0.063 W, AEC-Q200 Grade 0, 0402; Manufacturer: Vishay-Dale; Power_W: 63mW; TempCo: 200 ppm/C; Value_Code: 47k0; Value: 47k; EIA_Code: E24; SizeX_mm: 1; SizeY_mm: 0.5; SizeZ_mm: 0.6; Value2: 0.063W; AEC Qualified: Y; VDC_V: 50V; AEC Category: Q200; AEC Grade: 0
RT1-RT3 = CMP-0054545-2: Thermistor NTC, 10.0k ohm, 0.5%, 0603; Manufacturer: MuRata; TaMax_C: 125°C; SizeX_mm: 1.6; SizeY_mm: 0.8; TaMin_C: -40°C; Power_W: 100mW; SizeZ_mm: 1; SizeArea_mm2: 1.28; SizeAreaWB_mm2: 4.68; U/M: EA
U10 = CMP-0039653-1: 16 MHz Mixed Signal Microcontroller with 16 KB Flash, 512 B SRAM and 24 GPIOs, -40 to 85 degC, 32-pin QFN (RHB), Green (RoHS & no Sb/Br); Manufacturer: Texas Instruments; Temp Sensor: Yes; Frequency(MHz): 16; SRAM(B): 512; USCI_A (UART/LIN/IrDA/SPI): 1; ADC: 10-bit SAR; ADC Channels: 8; SubFamily: Value Line; Timers - 16-bit: 2; GPIO: 24
U11 = CMP-0093065-1: RCVR OPT DC-50MBD 1MM POF; Manufacturer: Broadcom; SizeZ_mm: 7.6mm; Sensing Distance: 50m; Fall Time: 5ns; LambdaD: 685nm; Max Supply Voltage: 5.25V; TaMin_C: -40°C; TaMax_C: +85°C; AEC Qualified: No; Standoff Height: 0.6mm; Min Supply Voltage: 3.135V
U12 = CMP-0093064-1: Fiber Optic Transmitter with Driver 650nm 50MBd 3.135V ~ 3.465V, 4.75V ~ 5.25V 21 mA; Manufacturer: Broadcom; TaMax_C: +85°C; SizeZ_mm: 7.6mm; AEC Qualified: No; Fall Time: 5ns; TaMin_C: -40°C; LambdaD: 685nm; Standoff Height: 0.6mm
Y3 = CMP-0078856-1: Crystal, 32.768 KHz, 20 ppm, SMD; Manufacturer: ECS Inc.; SizeAreaWB_mm2: 10.5; SizeArea_mm2: 4.8; Frequency Tolerance: 20 ppm; AEC Category: Q200; TaMax_C: 85°C; SizeZ_mm: 0.9; TaMin_C: -40°C; SizeY_mm: 1.5; SizeX_mm: 3.2

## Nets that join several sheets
14_4V: TAS6584Q1PHD_1 (L1.2), PowerSupplies_Boostcontroller (18 pins), PowerSupplies_Powerstage (12 pins)
BAT_IN: PowerSupplies_Boostcontroller (5 pins), SPDIF and Interface (J1.1 J1.3 J1.5 J1.7)
GND: TAS6584Q1PHD_1 (69 pins), TAS6584Q1PHD_2 (67 pins), PowerSupplies_Boostcontroller (41 pins), PowerSupplies_Powerstage (44 pins), SPDIF and Interface (32 pins), ADC (24 pins), MCU (32 pins)
PVDD: TAS6584Q1PHD_1 (20 pins), TAS6584Q1PHD_2 (20 pins), PowerSupplies_Powerstage (J5.2 R103.2 R104.2 R105.2)
V_boost: PowerSupplies_Boostcontroller (R61.1), PowerSupplies_Powerstage (9 pins)
VCC: TAS6584Q1PHD_1 (11 pins), TAS6584Q1PHD_2 (8 pins), PowerSupplies_Boostcontroller (C143.1 D5.1 U6.4), SPDIF and Interface (L15.2 R120.2 R121.2), ADC (L16.2), MCU (L17.2)
~{FAULT1}: TAS6584Q1PHD_1 (R6.1 U1.61), MCU (R158.1)
~{FAULT2}: TAS6584Q1PHD_2 (R35.1 U2.61), MCU (R159.1)
~{STBY1}: TAS6584Q1PHD_1 (R4.1 U1.60), MCU (R147.2)
~{STBY2}: TAS6584Q1PHD_2 (R33.1 U2.60), MCU (R146.2)
Audio_IN1+: SPDIF and Interface (J1.10), ADC (C190.1 R128.2)
Audio_IN1-: SPDIF and Interface (J1.9), ADC (C192.1 R130.2)
Audio_IN2+: SPDIF and Interface (J1.12), ADC (C191.1 R129.2)
Audio_IN2-: SPDIF and Interface (J1.11), ADC (C193.1 R131.2)
ClassH_tracking: TAS6584Q1PHD_1 (R5.1 U1.10), TAS6584Q1PHD_2 (U2.10), PowerSupplies_Boostcontroller (R64.1)
CSN1: PowerSupplies_Boostcontroller (C130.2 U4.3), PowerSupplies_Powerstage (R91.2)
CSN2: PowerSupplies_Boostcontroller (C142.2 U5.3), PowerSupplies_Powerstage (R92.2)
CSP1: PowerSupplies_Boostcontroller (C130.1 U4.4), PowerSupplies_Powerstage (R87.2)
CSP2: PowerSupplies_Boostcontroller (C142.1 U5.4), PowerSupplies_Powerstage (R88.2)
GPIO_1: TAS6584Q1PHD_1 (R2.1 U1.9), SPDIF and Interface (R126.1), MCU (R148.2)
GPIO_3: TAS6584Q1PHD_1 (R7.1 U1.62), MCU (R149.2)
GPIO_4: TAS6584Q1PHD_2 (R32.1 U2.9), SPDIF and Interface (R125.1), MCU (R150.2)
GPIO_6: TAS6584Q1PHD_2 (R36.1 U2.62), MCU (R151.2)
HO1: PowerSupplies_Boostcontroller (U4.19), PowerSupplies_Powerstage (D8.1 R97.1)
HO2: PowerSupplies_Boostcontroller (U5.19), PowerSupplies_Powerstage (D9.1 R98.1)
LO1: PowerSupplies_Boostcontroller (U4.16), PowerSupplies_Powerstage (D6.1 R95.1)
LO2: PowerSupplies_Boostcontroller (U5.16), PowerSupplies_Powerstage (D7.1 R96.1)
LRCLK: TAS6584Q1PHD_1 (U1.6), TAS6584Q1PHD_2 (U2.6), SPDIF and Interface (C186.1 R116.2), ADC (R140.1)
MCU_SCL: ADC (U9.24), MCU (R144.1 R157.1 U10.21)
MCU_SDA: ADC (U9.23), MCU (R145.1 R160.1 U10.22)
SCL: TAS6584Q1PHD_1 (R1.1 U1.13), TAS6584Q1PHD_2 (U2.13), SPDIF and Interface (R120.1 R123.1), MCU (R144.2)
SCLK: TAS6584Q1PHD_1 (U1.5), TAS6584Q1PHD_2 (U2.5), SPDIF and Interface (C185.1 R115.2), ADC (R141.1)
SDA: TAS6584Q1PHD_1 (R3.1 U1.12), TAS6584Q1PHD_2 (U2.12), SPDIF and Interface (R121.1 R122.1), MCU (R145.2)
SDIN: TAS6584Q1PHD_1 (U1.7), TAS6584Q1PHD_2 (U2.7), SPDIF and Interface (C188.1 R117.2 R125.2 R126.2), ADC (R139.1)
SPK_OUT1+: TAS6584Q1PHD_1 (C49.1 C57.1 R30.2), SPDIF and Interface (J1.14)
SPK_OUT1-: TAS6584Q1PHD_1 (C50.1 C58.1 R31.2), SPDIF and Interface (J1.13)
SPK_OUT2+: TAS6584Q1PHD_1 (C47.1 C55.1 R28.2), SPDIF and Interface (J1.16)
SPK_OUT2-: TAS6584Q1PHD_1 (C48.1 C56.1 R29.2), SPDIF and Interface (J1.15)
SPK_OUT3+: TAS6584Q1PHD_1 (C45.1 C53.1 R26.2), SPDIF and Interface (J1.18)
SPK_OUT3-: TAS6584Q1PHD_1 (C46.1 C54.1 R27.2), SPDIF and Interface (J1.17)
SPK_OUT4+: TAS6584Q1PHD_1 (C43.1 C51.1 R24.2), SPDIF and Interface (J1.20)
SPK_OUT4-: TAS6584Q1PHD_1 (C44.1 C52.1 R25.2), SPDIF and Interface (J1.19)
SPK_OUT5+: TAS6584Q1PHD_2 (C107.1 C115.1 R59.2), SPDIF and Interface (J2.2)
SPK_OUT5-: TAS6584Q1PHD_2 (C108.1 C116.1 R60.2), SPDIF and Interface (J2.1)
SPK_OUT6+: TAS6584Q1PHD_2 (C105.1 C113.1 R57.2), SPDIF and Interface (J2.4)
SPK_OUT6-: TAS6584Q1PHD_2 (C106.1 C114.1 R58.2), SPDIF and Interface (J2.3)
SPK_OUT7+: TAS6584Q1PHD_2 (C103.1 C111.1 R55.2), SPDIF and Interface (J2.6)
SPK_OUT7-: TAS6584Q1PHD_2 (C104.1 C112.1 R56.2), SPDIF and Interface (J2.5)
SPK_OUT8+: TAS6584Q1PHD_2 (C101.1 C109.1 R53.2), SPDIF and Interface (J2.8)
SPK_OUT8-: TAS6584Q1PHD_2 (C102.1 C110.1 R54.2), SPDIF and Interface (J2.7)
SW1: PowerSupplies_Boostcontroller (C132.2 R77.1), PowerSupplies_Powerstage (12 pins)
SW2: PowerSupplies_Boostcontroller (C144.2 R84.1), PowerSupplies_Powerstage (12 pins)
VBAT: TAS6584Q1PHD_1 (C16.1 C18.1 L1.1 U1.21), TAS6584Q1PHD_2 (C74.1 C76.1 U2.21)

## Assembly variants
001: not fitted FID1 FID2 FID3 FID4 FID5 FID6 J6 R72 R76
